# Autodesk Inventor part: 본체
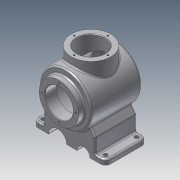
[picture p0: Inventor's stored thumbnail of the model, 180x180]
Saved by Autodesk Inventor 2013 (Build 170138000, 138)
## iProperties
Created: 2018-08
Part Number: 본체
Material: 알루미늄 6061
Document SubType Name: Modeling
Designer: Administrator
Density: 1 g/cm^3
Author: Administrator
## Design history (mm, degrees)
sketch "스케치1"
  geometry: L1 (-60, 0)-(60, 0); L2 (-60, 0)-(-60, 38); L3 (-60, 38)-(-48, 38); L4 (-48, 38)-(-48, 50); L5 (-48, 50)-(48.671, 50); A1 r 116 centre (-56, 0) between (60, 0) and (48.671, 50); 2 further points
  constraints: 10 end point, 2 parallel, 2 perpendicular, 2 point on circle, 1 centre point, 1 coincident, 1 horizontal, 1 midpoint, 1 point on line
  dimensions: "d0" = 120 distance of L1.start L1.end; "d1" = 116 radius of A1; "d2" = 100 diameter of L5 L1; "d3" = 76 diameter of L3 L1; "d4" = 12 distance of L2.end L3.end
revolve "회전1" sketch "스케치1" stored, may be unused: angle "d5" = 90 deg
sketch "스케치2"
  geometry: L1 (-60, -38)-(-60, 38) reference; L2 (-60, 38)-(-48, 38) reference; L3 (-48, 38)-(-48, 50) reference; L4 (-48, 50)-(48.671, 50) reference; L5 (48.671, -50)-(-48, -50) reference; L6 (-48, -50)-(-48, -38) reference; L7 (-48, -38)-(-60, -38) reference; L8 (-60, 27)-(-38, 27); L9 (-38, 27)-(-38, 40); L10 (-38, 40)-(42.163, 40); L11 (-60, 0)-(50, 0); L12 (-60, -38)-(-60, 38) reference; L13 (-60, 38)-(-48, 38) reference; L14 (-48, 38)-(-48, 50) reference; L15 (-48, 50)-(48.671, 50) reference; L16 (48.671, -50)-(-48, -50) reference; L17 (-48, -50)-(-48, -38) reference; L18 (-48, -38)-(-60, -38) reference; L19 (-60, 27)-(-60, 0); A1 r 116 centre (-56, 0) between (48.671, -50) and (48.671, 50) reference; A2 r 116 centre (-56, 0) between (48.671, -50) and (48.671, 50) reference; A3 r 116 centre (-56, 0) between (48.671, -50) and (48.671, 50) reference; A4 r 106 centre (-56, 0) between (50, 0) and (42.163, 40); 1 further point
  constraints: 10 end point, 2 parallel, 2 perpendicular, 2 point on circle, 2 point on line, 1 centre point, 1 midpoint
  dimensions: "d8" = 110 distance of L11.start L11.end; "d9" = 80 diameter of L10 L11; "d10" = 54 diameter of L8 L11; "d11" = 22 distance of L8.start L8.end; "d12" = 106 radius of A4
revolve "회전2" sketch "스케치2" stored, may be unused: angle "d13" = 90 deg
sketch "스케치3"
  geometry: L1 (0, 0)-(0, 32.5); C1 r 38 at (0, 0) reference; 1 further point
  constraints: 2 end point, 1 coincident, 1 vertical
  dimensions: "d15" = 32.5 distance of L1.start L1.end
hole "구멍1" sketch "스케치3" at (0, 32.5) diameter "d16" = 3.242; stored, may be unused: countersink angle "d20" = 90 deg, drill point angle "d22" = 118 deg; dims "d17" = 8, "d18" = 4, "d19" = 2, "d21" = 10
node "작업 평면1"
sketch "스케치4"
  geometry: L1 (48, 50)-(48, -50) reference; L2 (48, 50)-(-48.671, 50) reference; C1 r 38 at (-2, 0); 1 further point
  constraints: 1 centre point, 1 coincident
  dimensions: "d27" = 76 diameter of C1; "d83" = 50 distance from line of L1 point (-2, 0); "d84" = 50 distance from line of point (-2, 0) L2
extrude "돌출1" join sketch "스케치4" stored distance "d28" = 10; taper "d29" = 0 deg
sketch "스케치5"
  geometry: C1 r 38 at (0, 0) reference; C2 r 27 at (0, 0)
  constraints: 1 centre point, 1 coincident
  dimensions: "d30" = 54 diameter of C2
extrude "돌출2" cut sketch "스케치5" stored distance "d31" = 10; taper "d32" = 0 deg
sketch "스케치6"
  geometry: L1 (0, 0)-(0, 32.5); C1 r 38 at (0, 0) reference; 1 further point
  constraints: 2 end point, 1 coincident, 1 vertical
  dimensions: "d33" = 32.5 distance of L1.start L1.end
hole "구멍2" sketch "스케치6" at (0, 32.5) diameter "d34" = 3.242; stored, may be unused: countersink angle "d38" = 90 deg, drill point angle "d40" = 118 deg; dims "d35" = 8, "d36" = 4, "d37" = 2, "d39" = 10
node "작업 평면2"
sketch "스케치7"
  geometry: 1 further point
sketch "스케치8"
  geometry: L1 (60, 38)-(60, -38) reference; L2 (48, 50)-(48, -50) reference; L3 (40, -70)-(-40, -70); L4 (-40, -70)-(-40, 70); L5 (-40, 70)-(40, 70); L6 (40, 70)-(40, -70); L7 (40, -70)-(-40, 70); L8 (-40, -70)-(40, 70); 3 further points
  constraints: 12 end point, 3 midpoint, 2 parallel, 1 coincident, 1 horizontal, 1 perpendicular
  dimensions: "d45" = 80 distance of L4.end L5.end; "d46" = 140 distance of L3.end L4.end; "d48" = 8 distance between parallel lines of L6 L2
extrude "돌출3" join sketch "스케치8" distance "d49" = 10; taper "d50" = 0 deg
fillet "모깎기1" dims "d51" = 10
sketch "스케치9"
  geometry: A1 r 10 centre (-30, -60) between (-40, -60) and (-30, -70) reference; A2 r 10 centre (30, -60) between (30, -70) and (40, -60) reference; A3 r 10 centre (30, 60) between (40, 60) and (30, 70) reference; A4 r 10 centre (-30, 60) between (-30, 70) and (-40, 60) reference; 5 further points
  constraints: 4 coincident
hole "구멍3" sketch "스케치9" at (30, -60), (-30, -60), (-30, 60), (30, 60) diameter "d52" = 8; stored, may be unused: countersink angle "d56" = 90 deg, drill point angle "d58" = 118 deg; dims "d53" = 8, "d54" = 4, "d55" = 2, "d57" = 10
sketch "스케치10"
  geometry: L1 (0, 10)-(120, 10) reference; L2 (0, 0)-(0, 10) reference; L3 (19.696, 52.41)-(-10, 10); L4 (10, 38.563)-(10, 10); L5 (-10, 10)-(-10, 0) reference; L6 (130, 0)-(130, 10) reference; L7 (100.304, 52.41)-(130, 10); L8 (110, 38.563)-(110, 10); A1 r 50 centre (60, 82) between (19.696, 52.41) and (100.304, 52.41) reference; A2 r 50 centre (60, 82) between (19.696, 52.41) and (100.304, 52.41) reference; 1 further point
  constraints: 8 end point, 5 point on line, 4 point on circle, 2 perpendicular
  dimensions: "d60" = 35 deg angle of L2 L3; "d61" = 20 distance from line of L5 L4.end; "d62" = 35 deg angle of L7 L6; "d63" = 20 distance between parallel lines of L6 L8
extrude "돌출4" join sketch "스케치10" distance "d64" = 80; taper "d65" = 0 deg
sketch "스케치11"
  geometry: L1 (120, 0)-(0, 0) reference; C1 r 12.5 at (32.5, 0); C2 r 17.5 at (82.5, 0); A1 r 50 centre (60, 82) between (19.696, 52.41) and (100.304, 52.41) reference
  constraints: 2 centre point, 2 point on line
  dimensions: "d66" = 25 diameter of C1; "d67" = 35 diameter of C2; "d68" = 22.5 horizontal distance of C2.centre A1.centre; "d69" = 27.5 horizontal distance of A1.centre C1.centre
extrude "돌출5" cut sketch "스케치11" stored distance "d70" = 80; taper "d71" = 0 deg
chamfer "모따기1" distance "d72" = 1; stored, may be unused: second distance "d73" = 2, angle "d74" = 45 deg
fillet "모깎기2" dims "d75" = 3
fillet "모깎기3" dims "d76" = 3
fillet "모깎기4" dims "d77" = 3
fillet "모깎기5" dims "d78" = 3
node "작업 평면3"
sketch "스케치12"
  geometry: C1 r 32.5 at (0, 0); 1 further point
  constraints: 1 centre point, 1 coincident, 1 other
  dimensions: "d80" = 65 diameter of C1
feature "엠보싱1" sketch "스케치12" dims "d0" = 120, "d1" = 116, "d2" = 100, "d3" = 76, "d4" = 12, "d8" = 110, "d9" = 80, "d10" = 54, "d11" = 22, "d12" = 106, "d81" = 0.5, "d82" = 0
node "솔리드1"
pattern_circular "원형 패턴1" dims angle "d24" = 360 deg
pattern_circular "원형 패턴2" dims angle "d42" = 360 deg
node "투영된 루프1"
node "절단 모서리 투영1"
node "절단 모서리 투영2"
other parameters: "d26" = 65, "d44" = -82, "d79" = 63
